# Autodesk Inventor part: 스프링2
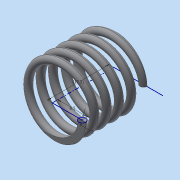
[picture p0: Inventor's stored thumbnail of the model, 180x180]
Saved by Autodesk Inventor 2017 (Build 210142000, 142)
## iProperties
Part Number: 스프링2
Material: 일반
Document SubType Name: Modeling
Designer: MRC
Density: 1 g/cm^3
Appearance: 기본값
Author: MRC
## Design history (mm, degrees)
sketch "스케치1"
  geometry: L1 (0, 0)-(0, 17.5); L2 (0, 0)-(8.5, 0); L3 (0, 17.5)-(14, 17.5); C1 r 1 at (8.5, 0)
  constraints: 6 end point, 2 horizontal, 1 centre point, 1 coincident, 1 vertical
  dimensions: "d0" = 17.5 distance of L1.start L1.end (derived); "d1" = 8.5 distance of L1.start L2.end; "d2" = 2 diameter of C1
feature "코일1" sketch "스케치1" pitch "d3" = 10; turns "d5" = 5; dims "d4" = 17.5 (= d0), "d6" = 0, angle "d7" = 90 deg, angle "d8" = 90 deg, "d9" = 0, "d10" = 0
sketch "스케치2"
  geometry: L1 (17.5, 11)-(0, 11); L2 (0, 11)-(0, -11); L3 (0, -11)-(17.5, -11); L4 (17.5, -11)-(17.5, 11); 2 further points
  constraints: 8 end point, 2 parallel, 1 coincident, 1 horizontal, 1 midpoint, 1 perpendicular
  dimensions: "d11" = 17.5 distance of L2.end L3.end (= d0); "d12" = 22 distance between parallel lines of L3 L1
extrude "돌출1" sketch "스케치2" stored distance "d13" = 50; taper "d14" = 0 deg
node "솔리드1"
